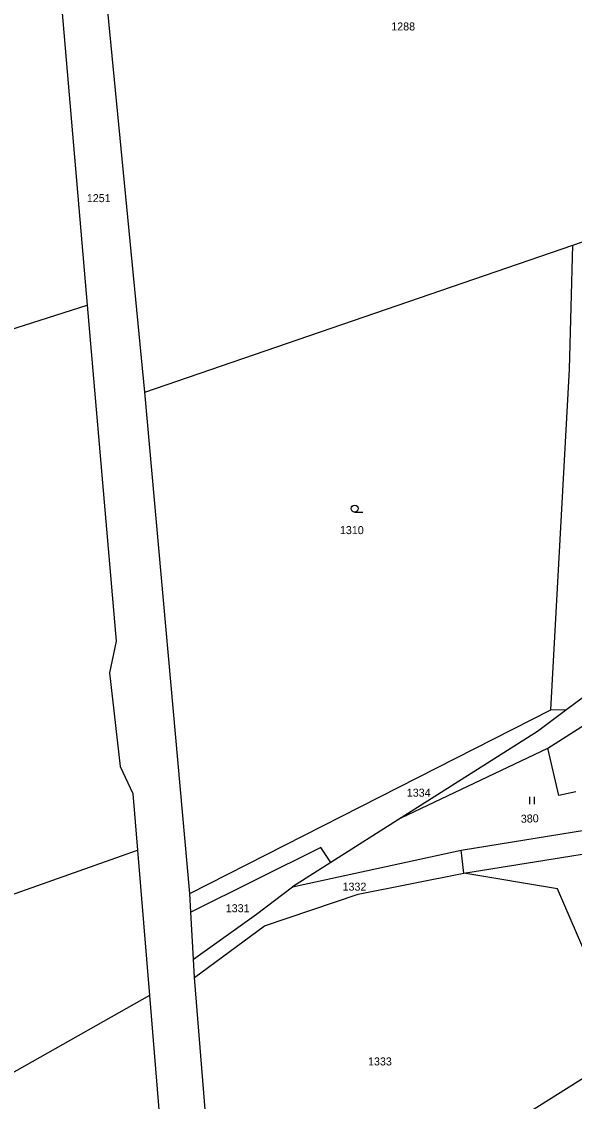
# Model space of a CAD drawing. Extents: x -520431 to -517205, y -1075927 to -1074013.
# Drawn here: x -518108.8 to -517991.5, y -1075237.3 to -1075007.9 of the extents above; entities that cross this region are included whole.
import ezdxf

# ---------------------------------------------------------------- set-up
doc = ezdxf.new("R2010")
doc.units = 0
for name, color, linetype in [('Hranice parcel', 7, 'Continuous'), ('Parcelní čísla', 7, 'Continuous'), ('Značky kultur', 7, 'Continuous')]:
    doc.layers.add(name, color=color, linetype=linetype)

msp = doc.modelspace()

# ---------------------------------------------------------------- linework, layer by layer
at = {"layer": 'Hranice parcel'}
for p, q in [((-518110.95, -1074881.98), (-518094.89, -1075068.19)), ((-518082.67, -1075086.62), (-518091.7, -1074993.89)), ((-518082.67, -1075086.62), (-517991.81, -1075055.38)), ((-518073.12, -1075193.16), (-518082.67, -1075086.62)), ((-517954.58, -1075125.31), (-517993.11, -1075154.09)), ((-518073.12, -1075193.16), (-517996.48, -1075154.17)), ((-517996.48, -1075154.17), (-517993.11, -1075154.09)), ((-518028.24, -1075177.1), (-517997.08, -1075162.29)), ((-517994.77, -1075172.35), (-517997.08, -1075162.29)), ((-517991.14, -1075171.54), (-517994.77, -1075172.35)), ((-518015.54, -1075183.98), (-517949.79, -1075173.23)), ((-518028.24, -1075177.1), (-518043.19, -1075186.57)), ((-518014.97, -1075188.83), (-517949.7, -1075178.44)), ((-518084.25, -1075183.95), (-518081.7, -1075214.82)), ((-518051.35, -1075191.74), (-518015.54, -1075183.98)), ((-518014.97, -1075188.83), (-518015.54, -1075183.98)), ((-518043.19, -1075186.57), (-518051.35, -1075191.74)), ((-518072.91, -1075197.1), (-518073.12, -1075193.16)), ((-518072.36, -1075207.09), (-518072.91, -1075197.1)), ((-518072.15, -1075211.03), (-518072.36, -1075207.09)), ((-518066.48, -1075280.79), (-518072.15, -1075211.03)), ((-518081.7, -1075214.82), (-518075.95, -1075284.43)), ((-518066.48, -1075280.79), (-517980.25, -1075226.41))]:
    msp.add_line(p, q, dxfattribs=at)
for points in [[(-517991.81, -1075055.38), (-517976.44, -1075050.07), (-517964.07, -1075047.14)], [(-517996.48, -1075154.17), (-517992.48, -1075081.79), (-517991.81, -1075055.38)], [(-518422.14, -1075172.6), (-518258.38, -1075120.35), (-518094.89, -1075068.19)], [(-518094.89, -1075068.19), (-518088.74, -1075139.53), (-518090.17, -1075146.29), (-518087.91, -1075166.16), (-518085.24, -1075171.9), (-518084.25, -1075183.95)], [(-517997.08, -1075162.29), (-517983.65, -1075153.73), (-517964.12, -1075146.21)], [(-517993.11, -1075154.09), (-517999.3, -1075158.71), (-518028.24, -1075177.1)], [(-518640.94, -1075380.3), (-518507.72, -1075333.58), (-518374.49, -1075286.85), (-518229.34, -1075235.39), (-518084.25, -1075183.95)], [(-518043.19, -1075186.57), (-518045.33, -1075183.36), (-518072.91, -1075197.1)], [(-518072.15, -1075211.03), (-518057.3, -1075200.03), (-518037.39, -1075193.28), (-518014.97, -1075188.83)], [(-517980.25, -1075226.41), (-517995.06, -1075192.19), (-518014.97, -1075188.83)], [(-518072.36, -1075207.09), (-518058.98, -1075197.52), (-518051.35, -1075191.74)], [(-518081.7, -1075214.82), (-518134.86, -1075244.89), (-518120.89, -1075302.8)]]:
    msp.add_lwpolyline(points, dxfattribs=at)
at = {"layer": 'Značky kultur'}
for p, q in [((-518038.13, -1075112.13), (-518036.38, -1075112.13)), ((-518000.97, -1075174.15), (-518000.97, -1075172.65)), ((-517999.97, -1075174.15), (-517999.97, -1075172.65))]:
    msp.add_line(p, q, dxfattribs=at)
msp.add_circle((-518038.13, -1075111.38), 0.75, dxfattribs=at)

# ---------------------------------------------------------------- texts
at = {"layer": 'Parcelní čísla'}
for s, p in [('1288', (-518030.36, -1075009.79)), ('1251', (-518094.99, -1075046.27)), ('1310', (-518041.26, -1075116.8)), ('1334', (-518027.06, -1075172.59)), ('1332', (-518040.7, -1075192.56)), ('1331', (-518065.5, -1075197.14)), ('1333', (-518035.29, -1075229.69))]:
    msp.add_text(s, height=1.7, dxfattribs=at).set_placement(p)
msp.add_text('380', height=1.7, rotation=2, dxfattribs=at).set_placement((-518002.82, -1075178.14))

doc.saveas('drawing.dxf')
